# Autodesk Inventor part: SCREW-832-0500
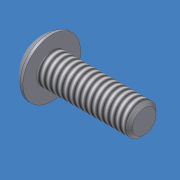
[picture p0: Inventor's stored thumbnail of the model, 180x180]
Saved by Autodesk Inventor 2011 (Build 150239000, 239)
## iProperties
Created: 2007-08
Part Number: SCREW-832-0500
Material: Stainless Steel
Document SubType Name: Modeling
Density: 8.08 g/cm^3
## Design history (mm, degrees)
feature "Base1"
thread "Thread1" dims "d0" = 25.4, "d1" = 0
body "Solid1"
